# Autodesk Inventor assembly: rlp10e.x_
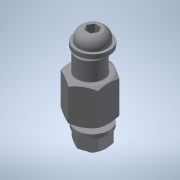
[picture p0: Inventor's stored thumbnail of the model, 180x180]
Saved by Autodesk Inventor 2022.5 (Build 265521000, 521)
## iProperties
Part Number: rlp10e.x_
Material: 一般
Document SubType Name: Assembly
Designer: ImaoCorp
Sending System: SOLIDWORKS 2017-2017317
MC: AMD64
MC_MODEL: Intel64 Family 6 Model 60 Stepping 3, GenuineIntel
OS: Windows_NT
FRU: Parasolid Version 29.0, build 201,  4-17-2017
FORMAT: text
GUISE: transmit
KEY: rlp10e
FILE: rlp10e.x_t
DATE: Wed Sep 04 15:58:26 2019
Author: ImaoCorp
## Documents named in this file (3)
- X:\14_SW2022-Inv2022\00_全2023-1023新製品(TCC)まで\r\rlp10e\RLP10E.iam
- X:\14_SW2022-Inv2022\00_全2023-1023新製品(TCC)まで\r\rlp10e\rlp10e_01.ipt
- X:\14_SW2022-Inv2022\00_全2023-1023新製品(TCC)まで\r\rlp10e\rlp10e_02.ipt
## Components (2 placed, 2 different names)
1. rlp10e_01
2. rlp10e_02
